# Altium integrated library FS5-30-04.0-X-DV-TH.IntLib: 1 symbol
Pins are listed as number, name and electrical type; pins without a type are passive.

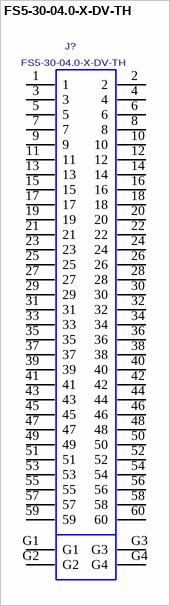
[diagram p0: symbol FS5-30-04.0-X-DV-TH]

## FS5-30-04.0-X-DV-TH
designator J?
FS5 SOCKET FLOATING ASSEMBLY; MANUFACTURER: SAMTEC
footprint FS5-30-04.0-X-DV-TH
pins: 1, 2, 3, 4, 5, 6, 7, 8, 9, 10, 11, 12, 13, 14, 15, 16, 17, 18, 19, 20, 21, 22, 23, 24, 25, 26, 27, 28, 29, 30, 31, 32, 33, 34, 35, 36, 37, 38, 39, 40, 41, 42, 43, 44, 45, 46, 47, 48, 49, 50, 51, 52, 53, 54, 55, 56, 57, 58, 59, 60, G1, G2, G3, G4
